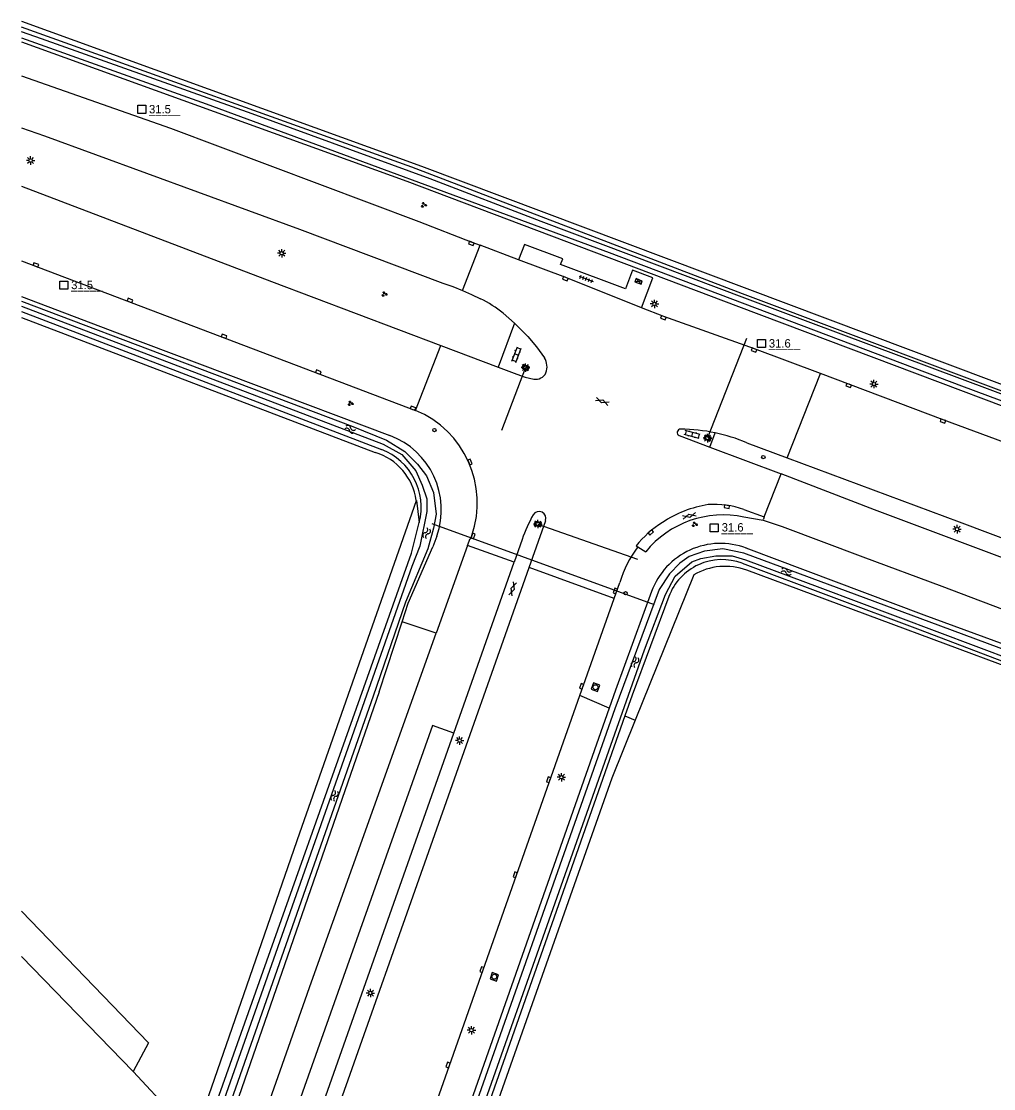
# Model space of a CAD drawing. Extents: x 130998 to 133001, y 398999 to 403002.
# Drawn here: x 131000 to 131144.6, y 400756.3 to 400915.1 of the extents above; entities that cross this region are included whole.
import ezdxf

# ---------------------------------------------------------------- set-up
doc = ezdxf.new("R2010")
doc.units = 0
for name, color, linetype in [('gg-afsc-erfafscheiding', 7, 'Continuous'), ('gg-afsc-hekwerk', 7, 'Continuous'), ('gg-knt-onverhard', 7, 'Continuous'), ('gg-knt-verharding', 7, 'Continuous'), ('gg-kntw-bovenkant insteek waterloop', 7, 'Continuous'), ('gg-kntw-waterlijn', 7, 'Continuous'), ('gg-kwrk-duiker nz buis', 7, 'Continuous'), ('gt-anno-nummer hm paal', 7, 'Continuous'), ('gt-grn-groengrens', 7, 'Continuous'), ('gt-grn-weggrens', 7, 'Continuous'), ('gt-knt-lijn portaal', 7, 'Continuous'), ('gt-symb-gesloten verharding', 7, 'Continuous'), ('gt-symb-groenvak', 7, 'Continuous'), ('gt-symb-hm paal', 7, 'Continuous'), ('gt-symb-klinker verharding', 7, 'Continuous'), ('gt-symb-kolk', 7, 'Continuous'), ('gt-symb-lichtmast', 7, 'Continuous'), ('gt-symb-rioolschacht', 7, 'Continuous'), ('gt-symb-tegel verharding', 7, 'Continuous'), ('gt-symb-verkeersregelinstallatiekast', 7, 'Continuous'), ('gt-symb-verkeersregelinstallatiepaal', 7, 'Continuous'), ('gt-symb-watersymbool', 7, 'Continuous'), ('gt-symb-wegwijzer', 7, 'Continuous')]:
    doc.layers.add(name, color=color, linetype=linetype)

# ---------------------------------------------------------------- blocks, each defined once
blk = doc.blocks.new('gt0-WA')
at = {"layer": 'gt-symb-watersymbool'}
for centre, start, end in [((-0.32, 0.02), 28.0725, 151.9275), ((0.43, 0.42), 208.0725, 331.9275), ((-0.32, -0.43), 28.0725, 151.9275), ((0.43, -0.03), 208.0725, 331.9275)]:
    blk.add_arc(centre, 0.425, start, end, dxfattribs=at)
blk = doc.blocks.new('gt0-VIPAAL')
at = {"layer": 'gt-symb-verkeersregelinstallatiepaal'}
blk.add_circle((0, 0), 0.25, dxfattribs=at)
blk = doc.blocks.new('gt0-LMAST')
at = {"layer": 'gt-symb-lichtmast'}
for p, q in [((-0.18, 0.17), (-0.45, 0.44)), ((-0.01, 0.25), (-0.01, 0.62)), ((0.17, 0.17), (0.44, 0.44)), ((-0.26, 0), (-0.63, 0)), ((-0.18, -0.18), (-0.45, -0.45)), ((-0.01, -0.25), (-0.01, -0.63)), ((0.44, -0.45), (0.17, -0.18)), ((0.24, 0), (0.62, 0))]:
    blk.add_line(p, q, dxfattribs=at)
blk.add_circle((-0.01, 0), 0.25, dxfattribs=at)
blk = doc.blocks.new('gt0-KOLK')
at = {"layer": 'gt-symb-kolk'}
blk.add_lwpolyline([(0, 0), (0.37, 0), (0.37, 0.4), (-0.38, 0.4), (-0.38, 0), (0, 0)], dxfattribs=at)
blk = doc.blocks.new('gt0-GESVH1')
at = {"layer": 'gt-symb-gesloten verharding'}
for p, q in [((-0.99, -0.26), (0.01, 0.24)), ((0.01, -0.26), (-0.99, 0.24)), ((0.01, 0.24), (1.01, -0.26)), ((1.01, 0.24), (0.01, -0.26))]:
    blk.add_line(p, q, dxfattribs=at)
blk = doc.blocks.new('gt0-GRVAK')
at = {"layer": 'gt-symb-groenvak'}
for p, q in [((-0.11, 0.19), (-0.23, 0.24)), ((-0.18, 0.15), (0.09, 0.15)), ((-0.09, 0.21), (-0.16, 0.32)), ((-0.05, 0.21), (-0.05, 0.39)), ((0, 0.21), (0.06, 0.32)), ((0.01, 0.19), (0.13, 0.24)), ((0.26, -0.05), (0.2, 0.06)), ((0.3, -0.05), (0.3, 0.13)), ((0.35, -0.05), (0.41, 0.06)), ((-0.24, -0.23), (-0.36, -0.18)), ((-0.32, -0.26), (-0.05, -0.26)), ((-0.23, -0.21), (-0.29, -0.09)), ((-0.18, -0.2), (-0.18, -0.02)), ((-0.14, -0.21), (-0.07, -0.09)), ((-0.12, -0.23), (0, -0.18)), ((0.24, -0.07), (0.12, -0.02)), ((0.17, -0.11), (0.44, -0.11)), ((0.37, -0.07), (0.49, -0.02))]:
    blk.add_line(p, q, dxfattribs=at)
blk = doc.blocks.new('gt0-HMpaal')
at = {"layer": 'gt-symb-hm paal'}
blk.add_lwpolyline([(-0.6, 0.6), (0.6, 0.6), (0.6, -0.6), (-0.6, -0.6)], close=True, dxfattribs=at)
blk = doc.blocks.new('gt0-RS')
at = {"layer": 'gt-symb-rioolschacht'}
blk.add_lwpolyline([(-0.5, -0.5), (0.5, -0.5), (0.5, 0.5), (-0.5, 0.5)], close=True, dxfattribs=at)
blk.add_circle((0, 0), 0.375, dxfattribs=at)
blk = doc.blocks.new('gt0-KL1')
at = {"layer": 'gt-symb-klinker verharding'}
for p, q in [((-1.15, 0.3), (1.15, 0.3)), ((-1, -0.3), (-1, 0.3)), ((-0.5, 0.3), (-0.5, 0.45)), ((0, -0.3), (0, 0.3)), ((0.5, 0.3), (0.5, 0.45)), ((1, -0.3), (1, 0.3)), ((-1.15, -0.3), (1.15, -0.3)), ((-0.5, -0.45), (-0.5, -0.3)), ((0.5, -0.45), (0.5, -0.3))]:
    blk.add_line(p, q, dxfattribs=at)
blk = doc.blocks.new('gt0-WW')
at = {"layer": 'gt-symb-wegwijzer'}
blk.add_lwpolyline([(-0.5, 0.3), (-0.5, -0.29), (0.5, -0.29), (0.5, 0.3), (-0.5, 0.3)], dxfattribs=at)
blk.add_lwpolyline([(-0.42, -0.21), (0.42, -0.21), (0.42, 0.21), (-0.42, 0.21)], close=True, dxfattribs=at)
blk = doc.blocks.new('gt0-TEG1')
at = {"layer": 'gt-symb-tegel verharding'}
for p, q in [((-1.12, 0), (1.12, 0)), ((-0.9, -0.25), (-0.9, 0.25)), ((-0.45, -0.25), (-0.45, 0.25)), ((0, -0.25), (0, 0.25)), ((0.45, -0.25), (0.45, 0.25)), ((0.9, -0.25), (0.9, 0.25))]:
    blk.add_line(p, q, dxfattribs=at)
blk = doc.blocks.new('gt0-VRIKST')
at = {"layer": 'gt-symb-verkeersregelinstallatiekast'}
for p, q in [((-0.5, -0.25), (0.5, 0.25)), ((-0.5, 0.25), (0.5, -0.25))]:
    blk.add_line(p, q, dxfattribs=at)
blk.add_lwpolyline([(0.5, 0.25), (-0.5, 0.25), (-0.5, -0.25), (0.5, -0.25)], close=True, dxfattribs=at)

msp = doc.modelspace()

# ---------------------------------------------------------------- linework, layer by layer
at = {"layer": 'gg-afsc-erfafscheiding'}
msp.add_line((131100.01, 400832.73), (131091.29, 400811.14), dxfattribs=at)
for points in [[(131026.17, 400750.3), (131041.44, 400794.37), (131058.75, 400843.83)], [(131091.29, 400811.14), (131087.81, 400802.53), (131060.02, 400723.73)]]:
    msp.add_lwpolyline(points, dxfattribs=at)
at = {"layer": 'gg-afsc-hekwerk'}
msp.add_line((131000, 400871.03), (131052.64, 400850.97), dxfattribs=at)
for points in [[(131000, 400915.09), (131059.52, 400893.52), (131156.32, 400857.16)], [(131297.89, 400767.45), (131292.37, 400765.36), (131196.7, 400800.42), (131107.9, 400833.44)]]:
    msp.add_lwpolyline(points, dxfattribs=at)
for centre, radius, start, end in [((131050.01, 400842.54), 8.83, 8.4242, 72.7308), ((131104.7, 400824.83), 9.19, 69.6024, 120.7066)]:
    msp.add_arc(centre, radius, start, end, dxfattribs=at)
at = {"layer": 'gg-knt-onverhard'}
for p, q in [((131000, 400782.7), (131018.93, 400763.13)), ((131000, 400775.99), (131016.63, 400758.87)), ((131018.93, 400763.13), (131016.63, 400758.87))]:
    msp.add_line(p, q, dxfattribs=at)
at = {"layer": 'gg-knt-verharding'}
for p, q in [((131073.96, 400879.63), (131068.26, 400881.77)), ((131000, 400879.47), (131058.63, 400857.22)), ((131071.68, 400871.67), (131073.35, 400870.2)), ((131073.35, 400870.2), (131070.9, 400863.66)), ((131062.41, 400866.86), (131070.9, 400863.66)), ((131097.84, 400853.46), (131102.42, 400851.74)), ((131102.42, 400851.74), (131103.21, 400853.86)), ((131107.89, 400852.4), (131113.92, 400850.15)), ((131102.42, 400851.74), (131112.99, 400847.78)), ((131107.45, 400842.47), (131110.47, 400841.36)), ((131107.47, 400841.36), (131110.32, 400840.89)), ((131110.47, 400841.36), (131110.37, 400841.02)), ((131075.52, 400833.84), (131077.99, 400840.82)), ((131110.32, 400840.89), (131110.37, 400841.02)), ((131074.49, 400838.03), (131073.29, 400834.66)), ((131066.37, 400837.1), (131061.72, 400824.1)), ((131091.46, 400837.05), (131091.71, 400836.9)), ((131091.71, 400836.9), (131092.86, 400836.19)), ((131025.13, 400691.09), (131075.52, 400833.84)), ((131064.31, 400809.21), (131073.29, 400834.66)), ((131088.15, 400829.21), (131089.02, 400831.63)), ((131083.07, 400814.82), (131088.15, 400829.21)), ((131021.29, 400687.34), (131064.31, 400809.21))]:
    msp.add_line(p, q, dxfattribs=at)
for points in [[(131000, 400906.96), (131022.2, 400899.19), (131059.13, 400885.33), (131067.01, 400882.24), (131068.26, 400881.77)], [(131000, 400899.27), (131003.43, 400898.07), (131041.36, 400884.15), (131062.71, 400876.16), (131064.18, 400875.65), (131065.63, 400875.07)], [(131000, 400890.55), (131037.21, 400876.38), (131062.41, 400866.86)], [(131092.26, 400872.48), (131093.94, 400876.95), (131090.92, 400878.09), (131089.86, 400875.28), (131080.21, 400878.92), (131080.52, 400879.74), (131074.85, 400881.9), (131073.96, 400879.63)], [(131092.26, 400872.48), (131080.98, 400876.99), (131073.96, 400879.63)], [(131065.63, 400875.07), (131066.97, 400874.47), (131068.29, 400873.81)], [(131118.84, 400862.7), (131109.03, 400866.38), (131095.56, 400871.17), (131092.26, 400872.48)], [(131073.35, 400870.2), (131075.31, 400868.23), (131076.62, 400866.67), (131077.8, 400865.02)], [(131070.9, 400863.66), (131073.71, 400862.59), (131074.94, 400862.18), (131076.21, 400861.87)], [(131237.99, 400818.49), (131221.59, 400824.48), (131179.4, 400840.08), (131165.43, 400845.33), (131137.13, 400855.83), (131118.84, 400862.7)], [(131113.92, 400850.15), (131139.49, 400840.62), (131181, 400825.04), (131199.68, 400818.14), (131200.52, 400817.89)], [(131199.64, 400815.41), (131187.41, 400819.86), (131151.51, 400833.2), (131126.89, 400842.42), (131112.99, 400847.78)], [(131110.32, 400840.89), (131113.16, 400839.96), (131125.16, 400835.44), (131136.89, 400831.06), (131148.81, 400826.58), (131172.95, 400817.56), (131196.8, 400808.69), (131220.61, 400799.93), (131245.15, 400790.87), (131269.28, 400782.06), (131315.76, 400765.13), (131337.86, 400757.06), (131348.96, 400753.02), (131360.64, 400748.84)], [(131066.37, 400837.1), (131066.74, 400838.16), (131066.86, 400838.18), (131067.01, 400838.6)], [(131032.94, 400743.22), (131043.18, 400772.23), (131061.72, 400824.1)], [(131051.07, 400724.08), (131063.66, 400759.77), (131068.69, 400773.98), (131073.64, 400788.08), (131083.07, 400814.82)]]:
    msp.add_lwpolyline(points, dxfattribs=at)
for centre, radius, start, end in [((131059.64, 400856.42), 19.43, 51.7245, 63.5806), ((131075.73, 400863.69), 2.46, 339.3736, 32.734), ((131076.5, 400863.53), 1.69, 260.2304, 335.2374), ((131052.91, 400843.45), 14.91, 341.0466, 67.4432), ((131098.05, 400853.92), 0.507, 88.9009, 245.7665), ((131097.8, 400828.23), 26.2, 78.087, 89.4306), ((131097.77, 400828.16), 26.28, 67.3376, 78.0464), ((131104.84, 400826.33), 17.09, 99.0443, 123.7312), ((131103.01, 400829.91), 13.33, 70.5403, 93.6784), ((131096.45, 400830.33), 23.28, 150.7615, 160.6805), ((131077, 400841.14), 1.03, 341.753, 146.8944), ((131104.43, 400826.73), 14.94, 78.2404, 140.7516), ((131102.9, 400828.19), 14.48, 121.4184, 142.2451), ((131104.26, 400827.15), 15.89, 142.1711, 163.6065)]:
    msp.add_arc(centre, radius, start, end, dxfattribs=at)
at = {"layer": 'gg-kntw-bovenkant insteek waterloop'}
for p, q in [((131000, 400871.91), (131053.57, 400851.4)), ((131061.78, 400838.5), (131061.19, 400836.9)), ((131053.22, 400815.35), (131056.63, 400825.77)), ((131053.22, 400815.35), (131029.48, 400746.84)), ((131087.42, 400812.91), (131054.79, 400720.11)), ((131089.78, 400811.8), (131056.88, 400718.24))]:
    msp.add_line(p, q, dxfattribs=at)
for points in [[(131287.75, 400806.21), (131288.01, 400807), (131285.99, 400808.42), (131241.6, 400824.58), (131154.04, 400856.98), (131107.24, 400874.55), (131058.06, 400893.4), (131000, 400914.23)], [(131000, 400912.02), (131057.35, 400891.3), (131106.66, 400872.66), (131152.99, 400855.21), (131188.02, 400842.21), (131240.63, 400822.77), (131284.79, 400806.62), (131287.75, 400806.21)], [(131000, 400874.15), (131014.26, 400868.73), (131054.82, 400853.47)], [(131027.23, 400749.19), (131058.03, 400835.98), (131059.19, 400840.53)], [(131056.63, 400825.77), (131057.55, 400828.55), (131061.19, 400836.9)], [(131293.49, 400768.03), (131215.87, 400796.43), (131195.52, 400804.01), (131175.39, 400811.66), (131134.29, 400826.75), (131107.83, 400836.73)], [(131107.2, 400834.48), (131133.68, 400824.58), (131174.92, 400808.88), (131194.6, 400801.69), (131214.99, 400794.13), (131253.7, 400780.16), (131291.48, 400766.15), (131293.49, 400768.03)], [(131093.75, 400830.28), (131088.36, 400815.6), (131087.42, 400812.91)], [(131096.31, 400829.51), (131090.86, 400814.87), (131089.78, 400811.8)]]:
    msp.add_lwpolyline(points, dxfattribs=at)
for centre, radius, start, end in [((131050.67, 400842.44), 11.79, 340.4857, 69.3971), ((131050.27, 400842.8), 9.21, 345.6764, 69.0237), ((131103.99, 400826.52), 10.91, 69.3502, 159.8457), ((131104.23, 400826.56), 8.46, 69.4845, 159.6045)]:
    msp.add_arc(centre, radius, start, end, dxfattribs=at)
at = {"layer": 'gg-kntw-waterlijn'}
for points in [[(131000, 400912.62), (131027.48, 400902.83), (131087.43, 400880.68), (131139.83, 400860.86), (131182.77, 400844.89), (131227.68, 400828.18), (131254.74, 400818.34), (131279.62, 400809.08), (131285.21, 400807.07), (131285.75, 400807.19), (131285.9, 400807.56), (131285.64, 400807.96), (131270.24, 400813.44), (131226.99, 400829.35), (131180.59, 400846.66), (131108, 400873.76), (131077.32, 400885.33), (131060.8, 400891.68), (131034.32, 400901.31), (131002.98, 400912.47), (131000, 400913.53)], [(131000, 400873.45), (131049.3, 400854.82), (131054.33, 400852.79), (131057.03, 400851.08), (131058.9, 400849.2), (131060.28, 400847.48), (131061.32, 400845.02), (131061.68, 400841.76), (131061.28, 400839.71), (131060.44, 400836.62), (131057.12, 400828.7), (131052.35, 400814.69), (131000, 400665.75)], [(131000, 400872.74), (131053.83, 400852.21), (131056.59, 400850.63), (131058.65, 400848.22), (131059.64, 400846.11), (131060.3, 400844.08), (131060.32, 400842.2), (131059.29, 400837.02), (131058.07, 400833.98), (131019.99, 400725.92), (131000, 400668.85)], [(131229.91, 400790.49), (131136.77, 400825.1), (131107.47, 400835.98), (131104.36, 400836.61), (131101.62, 400836.27), (131099.35, 400835.47), (131097.96, 400834.5), (131096.38, 400832.9), (131094.89, 400830.56), (131088.25, 400812.83), (131063.33, 400741.91)], [(131054.57, 400713.58), (131092.68, 400821.61), (131095.83, 400829.83), (131097.23, 400832.55), (131099.71, 400834.7), (131101.05, 400835.2), (131103.28, 400835.56), (131105.73, 400835.58), (131107.71, 400834.98), (131118.75, 400830.89), (131188.38, 400804.67)]]:
    msp.add_lwpolyline(points, dxfattribs=at)
at = {"layer": 'gg-kwrk-duiker nz buis'}
msp.add_line((131094.17, 400828.28), (131061.1, 400840.32), dxfattribs=at)
at = {"layer": 'gt-grn-groengrens'}
for p, q in [((131058.75, 400843.83), (131059.19, 400840.53)), ((131061.72, 400824.1), (131056.63, 400825.77)), ((131087.42, 400812.91), (131083.07, 400814.82)), ((131089.78, 400811.8), (131091.29, 400811.14))]:
    msp.add_line(p, q, dxfattribs=at)
msp.add_lwpolyline([(131016.63, 400758.87), (131022.53, 400752.51), (131020.54, 400750.86)], dxfattribs=at)
at = {"layer": 'gt-grn-weggrens'}
for p, q in [((131065.63, 400875.07), (131068.26, 400881.77)), ((131058.63, 400857.22), (131062.41, 400866.86)), ((131113.92, 400850.15), (131118.84, 400862.7)), ((131110.47, 400841.36), (131112.99, 400847.78)), ((131073.29, 400834.66), (131066.37, 400837.1)), ((131088.15, 400829.21), (131075.52, 400833.84)), ((131061.14, 400810.33), (131017.84, 400688.34)), ((131064.31, 400809.21), (131061.14, 400810.33))]:
    msp.add_line(p, q, dxfattribs=at)
at = {"layer": 'gt-knt-lijn portaal'}
for p, q in [((131102.1, 400853.18), (131107.89, 400867.94)), ((131074.99, 400863.59), (131071.44, 400854.24)), ((131076.83, 400840.31), (131091.64, 400835.08))]:
    msp.add_line(p, q, dxfattribs=at)

# ---------------------------------------------------------------- block references
at = {"layer": 'gt-symb-gesloten verharding'}
for p, rotation in [((131086.4, 400858.57), -21.407739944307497), ((131099.35, 400841.53), 13.702889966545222), ((131073.09, 400830.68), -108.12681251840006)]:
    msp.add_blockref('gt0-GESVH1', p, dxfattribs=dict(at, rotation=rotation))
at = {"layer": 'gt-symb-groenvak'}
for p in [(131059.85, 400887.78), (131053.99, 400874.52), (131048.96, 400858.25), (131100.14, 400840.27)]:
    msp.add_blockref('gt0-GRVAK', p, dxfattribs=at)
at = {"layer": 'gt-symb-hm paal'}
for p in [(131017.91, 400902), (131006.32, 400875.86), (131110.1, 400867.17), (131103.06, 400839.76)]:
    msp.add_blockref('gt0-HMpaal', p, dxfattribs=at)
at = {"layer": 'gt-symb-klinker verharding'}
for p, rotation in [((131073.66, 400865.5), 69.44395478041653), ((131099.77, 400853.63), 165.2272760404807)]:
    msp.add_blockref('gt0-KL1', p, dxfattribs=dict(at, rotation=rotation))
at = {"layer": 'gt-symb-kolk'}
for p, rotation in [((131067.01, 400882.24), 159.39030706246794), ((131002.09, 400878.67), -20.737148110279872), ((131080.98, 400876.99), 158.23049831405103), ((131016.08, 400873.38), -20.84426442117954), ((131095.56, 400871.17), 160.4232744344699), ((131030.1, 400868.04), -20.790725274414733), ((131109.03, 400866.38), 159.5177031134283), ((131044.12, 400862.72), -20.844264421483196), ((131123.12, 400861.11), 159.33669709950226), ((131058.2, 400857.36), -18.779117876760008), ((131137.13, 400855.83), 159.69875001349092), ((131066.55, 400849.46), -66.22952419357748), ((131104.97, 400843.09), 171.54573827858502), ((131067.01, 400838.6), -109.2143118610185), ((131093.49, 400839.19), -139.46084825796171), ((131088.53, 400830.29), 70.60447167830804), ((131083.52, 400816.1), 70.550431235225), ((131078.62, 400802.2), 70.55043123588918), ((131073.64, 400788.08), 70.6775176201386), ((131068.69, 400773.98), 70.49642676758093), ((131063.66, 400759.77), 70.60447167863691)]:
    msp.add_blockref('gt0-KOLK', p, dxfattribs=dict(at, rotation=rotation))
at = {"layer": 'gt-symb-lichtmast'}
for p in [(131001.38, 400894.39), (131038.73, 400880.59), (131094.18, 400873.05), (131074.99, 400863.59), (131126.82, 400861.13), (131102.06, 400853.09), (131076.83, 400840.31), (131139.18, 400839.55), (131065.2, 400808.11), (131080.34, 400802.65), (131051.93, 400770.55), (131066.96, 400765.02)]:
    msp.add_blockref('gt0-LMAST', p, dxfattribs=at)
at = {"layer": 'gt-symb-rioolschacht'}
for p, rotation in [((131085.4, 400816.04), 158.71983368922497), ((131070.35, 400772.97), 70.29604841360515)]:
    msp.add_blockref('gt0-RS', p, dxfattribs=dict(at, rotation=rotation))
at = {"layer": 'gt-symb-tegel verharding', "rotation": -20.247501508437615}
msp.add_blockref('gt0-TEG1', (131084.02, 400876.78), dxfattribs=at)
at = {"layer": 'gt-symb-verkeersregelinstallatiekast', "rotation": 158.54475267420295}
msp.add_blockref('gt0-VRIKST', (131091.8, 400876.4), dxfattribs=at)
at = {"layer": 'gt-symb-verkeersregelinstallatiepaal'}
for p, rotation in [((131061.43, 400854.28), -110.78838539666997), ((131110.36, 400850.28), 69.45151109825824), ((131089.88, 400830.01), -19.455701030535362)]:
    msp.add_blockref('gt0-VIPAAL', p, dxfattribs=dict(at, rotation=rotation))
at = {"layer": 'gt-symb-watersymbool'}
for p, rotation in [((131048.95, 400854.38), 159.39030706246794), ((131060.31, 400838.99), -110.42861714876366), ((131113.76, 400833.26), -10.433024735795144), ((131091.3, 400819.81), -110.42861714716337), ((131046.61, 400799.93), -108.12681251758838)]:
    msp.add_blockref('gt0-WA', p, dxfattribs=dict(at, rotation=rotation))
at = {"layer": 'gt-symb-wegwijzer'}
for p, rotation in [((131074.99, 400863.59), -20.55604521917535), ((131102.06, 400853.09), -20.323697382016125), ((131076.83, 400840.31), -8.781746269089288)]:
    msp.add_blockref('gt0-WW', p, dxfattribs=dict(at, rotation=rotation))

# ---------------------------------------------------------------- texts
at = {"layer": 'gt-anno-nummer hm paal'}
for s, p in [('31.5', (131018.99, 400901.4)), ('31.5', (131007.41, 400875.25)), ('31.6', (131111.18, 400866.56)), ('31.6', (131104.17, 400839.2))]:
    msp.add_text(s, height=1.25, dxfattribs=at).set_placement(p)
at = {"layer": 'gt-symb-hm paal'}
for p in [(131018.99, 400901.4), (131007.41, 400875.25), (131111.18, 400866.56), (131104.15, 400839.15)]:
    msp.add_text('_____', height=1.25, dxfattribs=at).set_placement(p)

doc.saveas('drawing.dxf')
